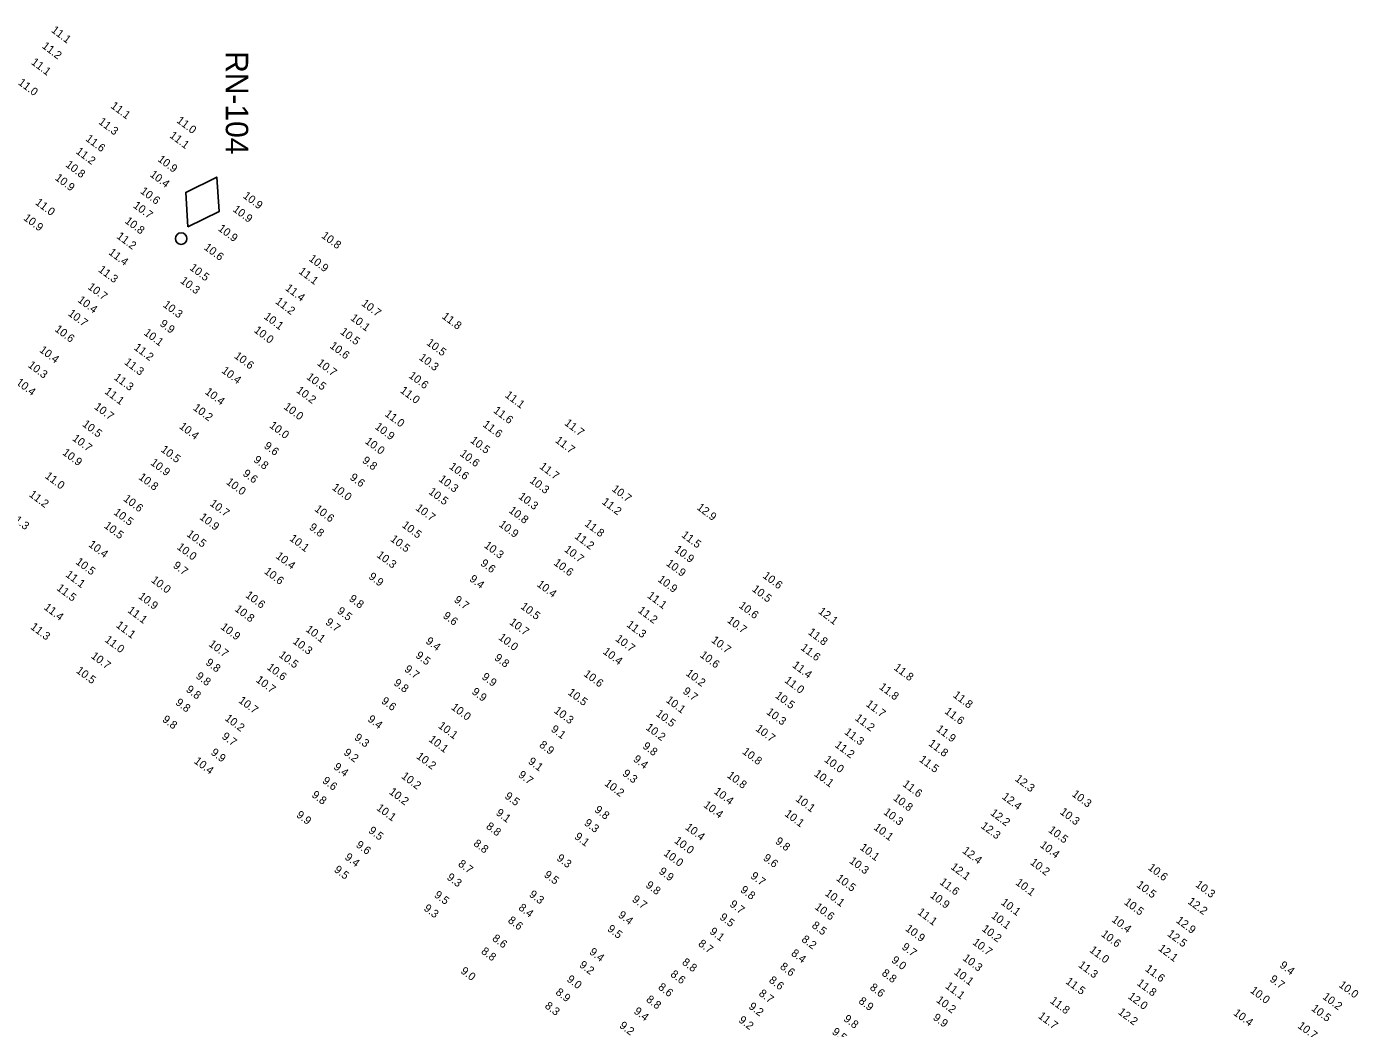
# Model space of a CAD drawing. Extents: x 988130 to 1132882, y 654656 to 841453.
# Drawn here: x 1035819 to 1036651, y 784449 to 785075 of the extents above; entities that cross this region are included whole.
import ezdxf

# ---------------------------------------------------------------- set-up
doc = ezdxf.new("R2010")
doc.units = 0
doc.layers.add('V-CHAN-NAID', color=7, linetype='Continuous')
doc.layers.add('V-TOPO-SOUN', color=7, linetype='Continuous')

msp = doc.modelspace()

# ---------------------------------------------------------------- linework, layer by layer
at = {"layer": 'V-CHAN-NAID'}
msp.add_lwpolyline([(1035919.71, 784949.99), (1035939.1, 784959.58), (1035937.71, 784981.17), (1035918.32, 784971.58)], close=True, dxfattribs=at)
msp.add_circle((1035915.51, 784942.72), 3.6, dxfattribs=at)

# ---------------------------------------------------------------- texts
msp.add_text('RN-104', height=14, rotation=270, dxfattribs=at).set_placement((1035943.33, 785059.79))
at = {"layer": 'V-TOPO-SOUN'}
for s, p in [('11.1 ', (1035833.93, 785072.16)), ('11.2 ', (1035828.15, 785062.22)), ('11.1 ', (1035821.39, 785052.11)), ('11.0 ', (1035813.27, 785039.35)), ('11.1 ', (1035871.05, 785024.82)), ('11.3 ', (1035863.48, 785014.85)), ('11.0 ', (1035912.22, 785015.68)), ('11.6 ', (1035855.37, 785004.32)), ('11.1 ', (1035907.83, 785006.31)), ('11.2 ', (1035849.27, 784996.39)), ('10.8 ', (1035842.87, 784988.09)), ('10.9 ', (1035900.41, 784991.47)), ('10.9 ', (1035836.26, 784979.84)), ('10.4 ', (1035895.51, 784982)), ('10.6 ', (1035889.56, 784971.54)), ('10.9 ', (1035953.67, 784968.63)), ('11.0 ', (1035823.95, 784964.49)), ('10.7 ', (1035885.07, 784962.58)), ('10.9 ', (1035947.32, 784960.23)), ('10.9 ', (1035816.58, 784954.82)), ('10.8 ', (1035879.9, 784952.95)), ('11.2 ', (1035874.76, 784943.4)), ('10.9 ', (1035938.1, 784948.2)), ('10.8 ', (1036002.67, 784943.74)), ('11.4 ', (1035869.75, 784933.32)), ('10.6 ', (1035929.32, 784936.41)), ('10.9 ', (1035994.79, 784929.33)), ('11.3 ', (1035863.32, 784922.52)), ('10.5 ', (1035920.35, 784923.68)), ('11.1 ', (1035988.43, 784921.48)), ('10.7 ', (1035856.72, 784911.74)), ('10.3 ', (1035914.52, 784915.55)), ('11.4 ', (1035980.09, 784910.96)), ('10.4 ', (1035850.47, 784903.59)), ('10.3 ', (1035903.71, 784900.57)), ('11.2 ', (1035973.9, 784902.65)), ('10.7 ', (1036027.66, 784901.41)), ('10.7 ', (1035844.41, 784895.18)), ('10.1 ', (1035966.73, 784893.2)), ('10.1 ', (1036020.81, 784892.35)), ('11.8 ', (1036077.92, 784893.37)), ('10.6 ', (1035836.12, 784885.35)), ('9.9', (1035901.73, 784888.73)), ('10.0 ', (1035960.55, 784884.69)), ('10.5 ', (1036014.4, 784883.7)), ('10.1 ', (1035891.75, 784883.09)), ('10.5 ', (1036068.31, 784876.83)), ('10.4 ', (1035826.53, 784872.39)), ('11.2 ', (1035885.57, 784873.87)), ('10.6 ', (1035948.21, 784868.63)), ('10.6 ', (1036007.89, 784874.94)), ('10.3 ', (1036063.62, 784867.6)), ('10.3 ', (1035819.34, 784862.9)), ('11.3 ', (1035879.55, 784864.75)), ('10.4 ', (1035940.3, 784859.46)), ('10.7 ', (1035999.98, 784864.2)), ('10.4 ', (1035811.91, 784852.11)), ('11.3 ', (1035873.07, 784855.2)), ('10.5 ', (1035993.34, 784855.48)), ('10.6 ', (1036057.2, 784856.33)), ('11.1 ', (1035867.24, 784846.42)), ('10.4 ', (1035929.96, 784846.2)), ('10.2 ', (1035987.02, 784847.14)), ('11.0 ', (1036051.85, 784847.04)), ('11.1 ', (1036117.33, 784844.17)), ('10.7 ', (1035860.75, 784836.82)), ('10.2 ', (1035922.5, 784836.21)), ('10.0 ', (1035979.12, 784836.85)), ('11.6 ', (1036110.07, 784834.54)), ('10.5 ', (1035853.36, 784826.03)), ('10.0 ', (1035970.18, 784825.18)), ('11.0 ', (1036042.25, 784832.41)), ('11.6 ', (1036103.42, 784825.81)), ('11.7 ', (1036154.48, 784826.74)), ('10.7 ', (1035847.11, 784817.16)), ('10.4 ', (1035913.85, 784824.65)), ('10.9 ', (1036036.07, 784824.39)), ('10.5 ', (1035902.38, 784810.16)), ('9.6', (1035966.78, 784812.41)), ('10.0 ', (1036029.89, 784815.35)), ('10.5 ', (1036095.66, 784815.86)), ('11.7 ', (1036148.66, 784815.92)), ('10.9 ', (1035840.9, 784808.25)), ('10.9 ', (1035895.9, 784801.94)), ('9.8', (1035960.25, 784803.74)), ('9.8', (1036028.13, 784803.31)), ('10.6 ', (1036089.17, 784807.59)), ('11.0 ', (1035830, 784793.65)), ('10.8 ', (1035888.51, 784792.88)), ('9.6', (1035953.54, 784795.16)), ('9.6', (1036020.43, 784792.74)), ('10.6 ', (1036082.47, 784799.53)), ('11.7 ', (1036138.86, 784799.61)), ('10.0 ', (1035943.16, 784789.94)), ('10.0 ', (1036009.29, 784786.43)), ('10.5 ', (1036069.61, 784783.79)), ('10.3 ', (1036075.92, 784791.68)), ('10.3 ', (1036132.72, 784790.85)), ('10.7 ', (1036184.04, 784785.58)), ('11.2 ', (1035820.05, 784782.14)), ('10.6 ', (1035878.98, 784779.41)), ('10.7 ', (1035932.96, 784776.48)), ('10.3 ', (1036125.73, 784780.85)), ('11.2 ', (1036177.85, 784777.51)), ('11.3 ', (1035807.85, 784768.31)), ('10.5 ', (1035872.92, 784770.95)), ('10.9 ', (1035926.56, 784767.91)), ('10.6 ', (1035998.37, 784773.06)), ('10.7 ', (1036061.5, 784773.68)), ('10.8 ', (1036119.71, 784772.14)), ('12.9 ', (1036237.13, 784774.03)), ('10.5 ', (1035866.89, 784762.59)), ('9.8', (1035994.99, 784761.59)), ('10.5 ', (1036052.95, 784762.96)), ('10.9 ', (1036113.52, 784763.42)), ('11.8 ', (1036167.06, 784763.82)), ('10.4 ', (1035857.16, 784750.83)), ('10.5 ', (1035918.48, 784757.34)), ('10.1 ', (1035982.76, 784754.6)), ('10.5 ', (1036045.73, 784754.27)), ('11.2 ', (1036160.76, 784756)), ('11.5 ', (1036227.55, 784756.85)), ('10.0 ', (1035912.43, 784749.28)), ('10.4 ', (1035974.11, 784743.64)), ('10.3 ', (1036037.22, 784744.27)), ('10.3 ', (1036104.27, 784750.29)), ('10.7 ', (1036154.34, 784747.76)), ('10.9 ', (1036223.18, 784747.73)), ('10.5 ', (1035849.18, 784740.03)), ('9.7', (1035910.01, 784737.69)), ('10.6 ', (1035966.89, 784734.07)), ('9.6', (1036102.04, 784739.12)), ('10.6 ', (1036147.75, 784739.41)), ('10.9 ', (1036217.97, 784739.08)), ('11.1 ', (1035842.86, 784732.06)), ('10.0 ', (1035896.31, 784728.67)), ('9.9', (1036032.13, 784730.79)), ('9.4', (1036095.11, 784729.31)), ('10.4 ', (1036137.26, 784726.02)), ('10.9 ', (1036212.76, 784729.06)), ('10.6 ', (1036278.32, 784731.34)), ('11.5 ', (1035837.29, 784723.62)), ('10.9 ', (1035888.33, 784718.51)), ('10.6 ', (1035955.24, 784719.21)), ('9.8', (1036019.86, 784716.97)), ('11.1 ', (1036206.2, 784718.92)), ('10.5 ', (1036271.61, 784723.03)), ('11.4 ', (1035829.34, 784711.63)), ('11.1 ', (1035881.63, 784709.76)), ('10.8 ', (1035948.51, 784710.61)), ('9.5', (1036012.5, 784709.29)), ('9.7', (1036085.51, 784716.28)), ('10.5 ', (1036127.05, 784712.15)), ('11.2 ', (1036200.35, 784709.76)), ('10.6 ', (1036263.38, 784712.71)), ('12.1 ', (1036313.02, 784709.12)), ('11.1 ', (1035874.36, 784700.45)), ('9.7', (1036005.18, 784702.31)), ('9.6', (1036078.56, 784706.34)), ('10.7 ', (1036120.08, 784702.31)), ('11.3 ', (1036193.26, 784700.81)), ('10.7 ', (1036256.05, 784703.55)), ('11.3 ', (1035820.95, 784699.41)), ('10.9 ', (1035939.71, 784699.39)), ('10.1 ', (1035992.86, 784697.89)), ('10.0 ', (1036113.23, 784692.81)), ('11.8 ', (1036306.59, 784696.07)), ('11.0 ', (1035867.35, 784691.42)), ('10.7 ', (1035932.25, 784688.68)), ('10.3 ', (1035984.74, 784690.38)), ('9.4', (1036067.78, 784690.47)), ('10.4 ', (1036178.46, 784683.96)), ('10.7 ', (1036186.27, 784691.96)), ('10.7 ', (1036246.19, 784691.09)), ('11.6 ', (1036302.02, 784686.4)), ('10.7 ', (1035858.77, 784681.27)), ('9.8', (1035930.34, 784677.08)), ('10.5 ', (1035976.06, 784681.87)), ('9.5', (1036061.47, 784681.56)), ('9.8', (1036110.71, 784680.07)), ('10.6 ', (1036239.09, 784681.88)), ('11.4 ', (1036296.8, 784675.49)), ('10.5 ', (1035849.47, 784672.11)), ('9.8', (1035924.25, 784668.63)), ('10.6 ', (1035968.65, 784674.18)), ('9.7', (1036054.5, 784672.99)), ('9.9', (1036102.82, 784668.17)), ('10.6 ', (1036166.46, 784670.04)), ('10.2 ', (1036230.28, 784670.42)), ('11.8 ', (1036360.2, 784673.92)), ('9.8', (1035918.1, 784660.25)), ('10.7 ', (1035961.75, 784666.32)), ('9.8', (1036047.82, 784664.38)), ('9.9', (1036096.6, 784658.84)), ('9.7', (1036228.4, 784659.16)), ('11.0 ', (1036291.92, 784666.03)), ('11.8 ', (1036351.03, 784661.92)), ('9.8', (1035911.52, 784652.15)), ('10.7 ', (1035950.9, 784653.42)), ('9.6', (1036040.05, 784653.07)), ('10.5 ', (1036156.58, 784658.43)), ('10.1 ', (1036217.81, 784653.7)), ('10.5 ', (1036286.06, 784656.46)), ('11.7 ', (1036342.74, 784651.18)), ('11.8 ', (1036397.14, 784656.8)), ('10.2 ', (1035942.4, 784642.33)), ('10.0 ', (1036083.72, 784649.22)), ('10.3 ', (1036147.92, 784647.08)), ('10.5 ', (1036211.55, 784645.15)), ('10.3 ', (1036280.61, 784646.27)), ('11.2 ', (1036335.92, 784642.44)), ('11.6 ', (1036391.91, 784646.67)), ('9.8', (1035903.26, 784641.61)), ('9.4', (1036031.51, 784641.74)), ('10.1 ', (1036075.6, 784637.62)), ('9.1', (1036146.02, 784635.47)), ('10.2 ', (1036205.28, 784636.54)), ('10.7 ', (1036273.81, 784635.82)), ('11.9 ', (1036386.65, 784635.64)), ('9.7', (1035940.47, 784630.98)), ('9.3', (1036023.22, 784630.24)), ('10.1 ', (1036069.67, 784629.16)), ('8.9', (1036138.71, 784625.71)), ('11.2 ', (1036323.35, 784625.69)), ('11.3 ', (1036329.31, 784633.76)), ('11.8 ', (1036381.82, 784626.55)), ('9.9', (1035933.6, 784620.96)), ('9.2', (1036016.58, 784620.87)), ('10.2 ', (1036061.96, 784618.6)), ('9.8', (1036203.26, 784624.91)), ('10.8 ', (1036265.55, 784621.49)), ('10.4 ', (1035923.08, 784615.61)), ('9.4', (1036010.24, 784611.97)), ('9.1', (1036131.79, 784615.36)), ('9.4', (1036197.39, 784616.78)), ('10.0 ', (1036316.75, 784616.48)), ('11.5 ', (1036376.02, 784616.59)), ('9.6', (1036003.22, 784603.32)), ('10.2 ', (1036052.6, 784606.19)), ('9.7', (1036125.59, 784607)), ('10.2 ', (1036179.47, 784601.64)), ('9.3', (1036190.7, 784607.82)), ('10.8 ', (1036256.05, 784606.66)), ('10.1 ', (1036310.39, 784607.63)), ('11.6 ', (1036365.65, 784601.23)), ('12.3 ', (1036435.87, 784604.56)), ('9.8', (1035996.58, 784594.46)), ('10.2 ', (1036044.94, 784596.38)), ('9.5', (1036117.16, 784593.67)), ('10.4 ', (1036247.82, 784596.6)), ('10.8 ', (1036359.77, 784592.54)), ('12.4 ', (1036427.73, 784593.35)), ('10.3 ', (1036471.4, 784594.96)), ('10.1 ', (1036037.05, 784586.34)), ('9.8', (1036173.22, 784585.17)), ('10.4 ', (1036241.29, 784588.18)), ('10.1 ', (1036298.81, 784591.95)), ('9.9', (1035986.99, 784581.96)), ('9.1', (1036111.66, 784583.29)), ('9.3', (1036166.75, 784576.94)), ('10.1 ', (1036291.98, 784582.63)), ('10.3 ', (1036353.76, 784583.71)), ('12.2 ', (1036420.49, 784583.22)), ('10.3 ', (1036463.97, 784583.86)), ('9.5', (1036032.06, 784572.15)), ('8.8', (1036105.5, 784574.8)), ('9.1', (1036160.75, 784568.38)), ('10.4 ', (1036229.89, 784574.26)), ('10.1 ', (1036347.65, 784574.17)), ('12.3 ', (1036414.54, 784575.11)), ('10.5 ', (1036456.71, 784572.54)), ('9.6', (1036024.23, 784563.24)), ('8.8', (1036097.65, 784564.09)), ('10.0 ', (1036223.06, 784565.87)), ('9.8', (1036286.1, 784565.47)), ('10.1 ', (1036338.97, 784561.62)), ('12.4 ', (1036402.99, 784559.58)), ('10.4 ', (1036451.44, 784563.19)), ('9.4', (1036017.24, 784555.57)), ('8.7', (1036088.03, 784551.37)), ('9.3', (1036149.56, 784554.94)), ('10.0 ', (1036216.4, 784557.98)), ('9.6', (1036278.56, 784555.05)), ('10.3 ', (1036332.36, 784553.25)), ('10.2 ', (1036445.35, 784552.37)), ('9.5', (1036010.58, 784547.76)), ('9.3', (1036080.97, 784542.99)), ('9.5', (1036141.67, 784544.61)), ('9.9', (1036213.42, 784546.68)), ('9.7', (1036270.69, 784543.8)), ('10.5 ', (1036324.17, 784542.39)), ('12.1 ', (1036395.71, 784549.5)), ('10.6 ', (1036518.94, 784549.05)), ('9.8', (1036205.22, 784538.1)), ('9.8', (1036264.34, 784535.12)), ('11.6 ', (1036388.82, 784540.03)), ('10.1 ', (1036436.25, 784539.68)), ('10.5 ', (1036511.77, 784538.28)), ('10.3 ', (1036548.56, 784538.46)), ('9.5', (1036073.12, 784531.98)), ('9.3', (1036132.39, 784532.33)), ('9.7', (1036196.71, 784529.22)), ('9.7', (1036257.61, 784526.15)), ('10.1 ', (1036317.21, 784532.98)), ('10.9 ', (1036382.8, 784531.77)), ('10.1 ', (1036427.1, 784527.35)), ('10.5 ', (1036504.02, 784527.49)), ('12.2 ', (1036543.76, 784527.87)), ('9.3', (1036066.57, 784523.65)), ('8.4', (1036125.76, 784523.99)), ('9.4', (1036188.01, 784519.42)), ('9.5', (1036251.35, 784518.04)), ('10.6 ', (1036310.8, 784524.48)), ('11.1 ', (1036374.98, 784521.25)), ('10.1 ', (1036421.02, 784518.97)), ('8.6', (1036119.14, 784516.09)), ('9.5', (1036181.26, 784510.77)), ('9.1', (1036245.12, 784509.13)), ('8.5', (1036308.92, 784512.92)), ('10.9 ', (1036367.39, 784510.98)), ('10.2 ', (1036415.15, 784510.82)), ('10.4 ', (1036496.23, 784516.59)), ('12.9 ', (1036536.47, 784516.08)), ('8.6', (1036109.36, 784504.81)), ('8.7', (1036238.02, 784501.54)), ('8.2', (1036302.55, 784504.21)), ('10.7 ', (1036409.34, 784502.41)), ('10.6 ', (1036489.67, 784507.54)), ('12.5 ', (1036530.99, 784507.69)), ('8.8', (1036102.43, 784496.76)), ('9.4', (1036170, 784496.37)), ('8.4', (1036296.05, 784495.54)), ('9.7', (1036365.15, 784499.47)), ('10.3 ', (1036403.22, 784492.53)), ('11.0 ', (1036482.4, 784497.63)), ('12.1 ', (1036525.37, 784498.63)), ('9.0', (1036089.61, 784484.46)), ('9.2', (1036163.72, 784488.27)), ('8.8', (1036227.9, 784489.92)), ('8.6', (1036289.07, 784487.21)), ('9.0', (1036358.69, 784491.25)), ('11.3 ', (1036475.41, 784488.28)), ('11.6 ', (1036517.16, 784485.82)), ('9.4', (1036601.16, 784488.05)), ('9.0', (1036155.91, 784479.32)), ('8.6', (1036220.67, 784482.44)), ('8.6', (1036282.16, 784478.67)), ('8.8', (1036352.61, 784483.12)), ('10.1 ', (1036397.79, 784483.79)), ('11.5 ', (1036467.48, 784477.96)), ('11.8 ', (1036512, 784476.96)), ('9.7', (1036594.97, 784479.36)), ('8.9', (1036148.91, 784471.18)), ('8.6', (1036212.95, 784474.42)), ('8.7', (1036275.83, 784470.44)), ('8.6', (1036345.16, 784474.21)), ('11.1 ', (1036392.29, 784475.11)), ('12.0 ', (1036506.46, 784468.61)), ('10.0 ', (1036582.78, 784472.33)), ('10.2 ', (1036627.96, 784468.39)), ('10.0 ', (1036638.11, 784475.8)), ('8.3', (1036142.18, 784462.69)), ('9.4', (1036197.8, 784459.33)), ('8.8', (1036205.48, 784466.7)), ('9.2', (1036269.5, 784462.32)), ('8.9', (1036338.18, 784465.67)), ('10.2 ', (1036386.71, 784466.36)), ('11.8 ', (1036457.78, 784465.88)), ('10.5 ', (1036620.95, 784461.09)), ('9.2', (1036263.23, 784453.85)), ('9.8', (1036328.78, 784454.6)), ('9.9', (1036384.65, 784455.36)), ('11.7 ', (1036450.33, 784456.38)), ('12.2 ', (1036500.28, 784458.88)), ('10.4 ', (1036572.28, 784458.28)), ('9.2', (1036188.76, 784450.38)), ('9.5', (1036321.56, 784446.46)), ('10.7 ', (1036612.44, 784450.24))]:
    msp.add_text(s, height=5, rotation=323, dxfattribs=at).set_placement(p)

doc.saveas('drawing.dxf')
